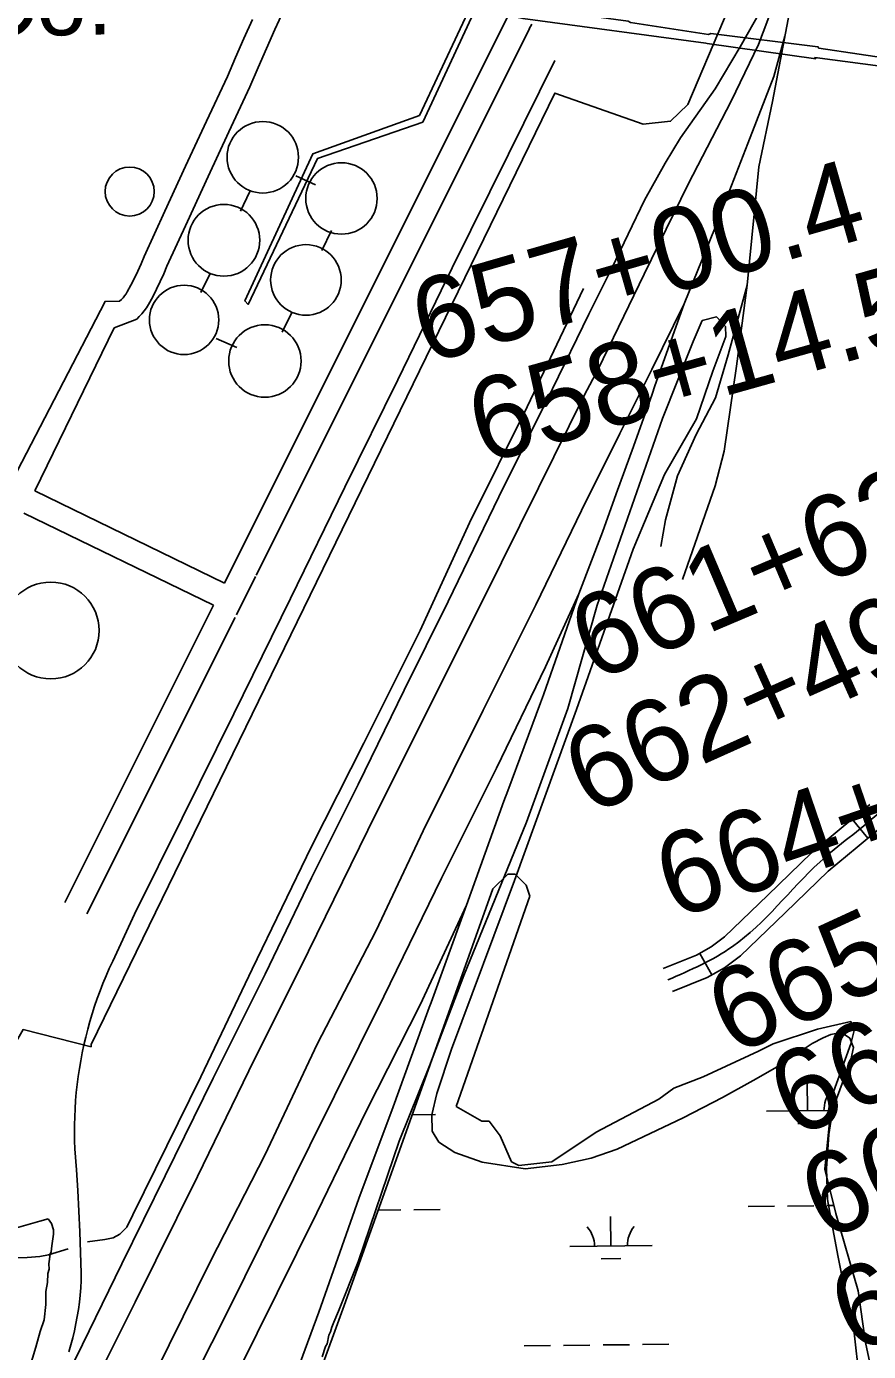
# Model space of a CAD drawing. Extents: x 3625074 to 3663148, y 511451 to 537151.
# Drawn here: x 3656305 to 3657328, y 518099 to 519708 of the extents above; entities that cross this region are included whole.
import ezdxf

# ---------------------------------------------------------------- set-up
doc = ezdxf.new("R2010")
doc.units = 0
for name, color, linetype in [('V-BLDG-IDEN', 7, 'Continuous'), ('V-DOMW-TANK', 7, 'Continuous'), ('V-RAIL-TRAK', 7, 'Continuous'), ('V-ROAD-CNTR', 7, 'Continuous'), ('V-SITE-OTLN', 7, 'Continuous'), ('V-SITE-VEGE', 7, 'Continuous'), ('V-SURV-IDEN', 7, 'Continuous'), ('V-TOPO-SHOR', 7, 'Continuous'), ('V-UTIL-LINE', 7, 'Continuous'), ('V-WETL-SWMP', 7, 'Continuous')]:
    doc.layers.add(name, color=color, linetype=linetype)

msp = doc.modelspace()

# ---------------------------------------------------------------- linework, layer by layer
at = {"layer": 'V-DOMW-TANK'}
for centre, radius in [((3656591.6538281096, 519549.49129885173), 43.424167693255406), ((3656429.9732665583, 519507.77570504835), 29.80810737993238), ((3656687.2301187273, 519499.4398599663), 43.37723661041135), ((3656544.445555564, 519448.61488410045), 43.558219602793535), ((3656644.1125855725, 519400.44507197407), 42.881477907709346), ((3656496.0472769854, 519351.92765908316), 42.10919878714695), ((3656594.2244595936, 519301.97549370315), 43.996236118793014), ((3656334.055766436, 518974.54792726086), 58.795414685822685)]:
    msp.add_circle(centre, radius, dxfattribs=at)
at = {"layer": 'V-RAIL-TRAK'}
for points in [[(3657229.676, 520658.132), (3657252.8000000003, 520496.53), (3657273.728, 520344.41500000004), (3657279.9220000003, 520260.462), (3657282.686, 520183.066), (3657281.509, 520116.364), (3657270.703, 520006.143), (3657266.718, 519958.156), (3657253.099, 519855.66000000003), (3657233.241, 519734.37700000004), (3657211.096, 519617.26900000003), (3657194.342, 519537.853), (3657179.991, 519394.039), (3657167.034, 519295.661), (3657152.223, 519192.59500000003), (3657141.438, 519150.27400000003), (3657101.637, 519036.429)], [(3656987.836, 519358.805), (3657015.6210000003, 519414.658), (3657055.4590000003, 519497.207), (3657080.463, 519542.23000000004), (3657099.313, 519573.19), (3657141.1040000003, 519632.678), (3657171.525, 519683.507), (3657197.1210000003, 519728.52), (3657216.19, 519771.876), (3657236.713, 519830.56), (3657251.932, 519889.925), (3657266.718, 519958.156)], [(3656982.394, 519261.009), (3656999.284, 519292.132), (3657055.0530000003, 519407.465), (3657108.356, 519516.93700000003), (3657160.912, 519617.566), (3657194.018, 519686.653), (3657205.176, 519716.568), (3657235.197, 519811.691), (3657251.932, 519889.925)], [(3656975.744, 519019.01300000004), (3657004.232, 519094.087), (3657021.146, 519140.488), (3657042.085, 519197.928), (3657064.644, 519261.82), (3657068.1890000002, 519271.863), (3657103.609, 519371.613), (3657141.264, 519464.238), (3657180.856, 519566.278), (3657212.407, 519647.792), (3657226.076, 519696.487)], [(3656355.954, 518098.38800000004), (3656358.473, 518106.813), (3656360.771, 518115.302), (3656362.841, 518123.851), (3656364.687, 518132.44800000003), (3656366.305, 518141.09500000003), (3656367.693, 518149.778), (3656368.852, 518158.49700000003), (3656369.782, 518167.242), (3656370.481, 518176.007), (3656370.947, 518184.791), (3656371.183, 518193.581), (3656370.3880000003, 518218.78), (3656369.395, 518243.97000000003), (3656368.201, 518269.15), (3656366.806, 518294.322), (3656365.213, 518319.482), (3656363.419, 518344.62700000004), (3656363.0500000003, 518354.41500000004), (3656362.884, 518364.206), (3656362.921, 518374), (3656363.157, 518383.789), (3656363.595, 518393.574), (3656364.232, 518403.347), (3656365.072, 518413.104), (3656366.11, 518422.842), (3656367.349, 518432.556), (3656368.787, 518442.245), (3656370.423, 518451.89900000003), (3656372.256, 518461.521), (3656374.288, 518471.101), (3656376.5160000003, 518480.639), (3656378.9390000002, 518490.12700000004), (3656381.556, 518499.565), (3656384.3680000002, 518508.944), (3656387.3680000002, 518518.267), (3656390.561, 518527.526), (3656393.944, 518536.715), (3656397.5160000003, 518545.837), (3656401.272, 518554.881), (3656405.215, 518563.84500000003), (3656409.339, 518572.727), (3656435.816, 518630.047), (3656493.5300000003, 518746.37700000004), (3656556.642, 518873.216), (3656625.489, 519013.365), (3656691.232, 519148.65400000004), (3656755.8710000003, 519279.121), (3656821.6, 519415.20900000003), (3656890.0870000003, 519553.353), (3656946.659, 519666.86100000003)], [(3657075.183, 519076.457), (3657081.069, 519108.82800000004), (3657095.595, 519162.30100000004), (3657118.33, 519212.678), (3657141.555, 519257.142), (3657157.238, 519309.41500000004), (3657179.991, 519394.039)], [(3656310.816, 517982.139), (3656372.809, 518107.145), (3656420.482, 518205.281), (3656473.19, 518311.914), (3656531.257, 518430.653), (3656594.3740000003, 518557.091), (3656650.876, 518674.197), (3656707.454, 518787.306), (3656763.602, 518902.009), (3656817.086, 519009.856), (3656878.5870000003, 519137.064), (3656943.611, 519268.337), (3656987.836, 519358.805)], [(3656979.058, 519120.315), (3657025.5870000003, 519213.966), (3657064.161, 519291.815), (3657103.609, 519371.613)], [(3655986.384, 517252.59500000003), (3656035.112, 517350.036), (3656107.0500000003, 517495.846), (3656160.204, 517600.087), (3656222.482, 517728.509), (3656286.7600000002, 517856.97000000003), (3656356.769, 517999.142), (3656436.436, 518158.704), (3656512.239, 518311.39), (3656574.525, 518439.411), (3656647.27, 518584.837), (3656719.183, 518731.847), (3656791.9280000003, 518877.273), (3656858.896, 519011.386), (3656926.615, 519147.914), (3656982.394, 519261.009)], [(3655992.255561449, 517127.89855132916), (3656024.125, 517191.59500000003), (3656102.625, 517349.533), (3656167.294, 517478.401), (3656227.723, 517599.186), (3656290.778, 517728.822), (3656355.839, 517858.096), (3656414.668, 517978.85000000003), (3656477.755, 518106.887), (3656528.549, 518209.082), (3656594.417, 518337.97500000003), (3656657.786, 518472.017), (3656729.472, 518610.222), (3656786.696, 518731.34500000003), (3656859.424, 518877.57), (3656923.309, 519005.623), (3656979.058, 519120.315)], [(3656448.759, 517948.681), (3656550.025, 518149.068), (3656648.9, 518349.006), (3656738.5470000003, 518529.963), (3656808.9250000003, 518673.743), (3656875.4990000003, 518807.449), (3656935.0870000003, 518930.216), (3656975.744, 519019.01300000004), (3656932.609, 518896.348), (3656929.146, 518886.499), (3656889.347, 518779.727), (3656884.688, 518767.23000000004), (3656838.983, 518640.82300000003), (3656835.745, 518631.869), (3656796.288, 518522.697), (3656793.98, 518516.37), (3656770.86, 518453.01300000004), (3656749.9790000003, 518395.788), (3656708.562, 518284.57800000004), (3656659.677, 518146.42), (3656609.924, 518011.444)], [(3656335.179, 517612.148), (3656389.4390000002, 517721.21), (3656457.549, 517858.145), (3656534.017, 518017.646), (3656584.787, 518121.041), (3656657.518, 518267.266), (3656717.483, 518391.242), (3656782.96, 518519.72500000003), (3656838.983, 518640.82300000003)]]:
    msp.add_lwpolyline(points, dxfattribs=at)
at = {"layer": 'V-ROAD-CNTR'}
for p, q in [((3657307.593, 518745.275), (3657326.81, 518722.239)), ((3657122.543, 518582.326), (3657137.1410000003, 518556.117))]:
    msp.add_line(p, q, dxfattribs=at)
for points in [[(3656579.1218022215, 519717.0201217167), (3656568.696051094, 519693.83725817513), (3656558.4944061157, 519670.55469874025), (3656548.642780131, 519647.4768950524), (3656523.286714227, 519593.22443723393), (3656497.9714443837, 519538.64704913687), (3656472.814376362, 519483.997799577), (3656447.7203644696, 519429.0706216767), (3656443.867774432, 519419.8423012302), (3656439.958806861, 519411.1222966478), (3656435.823743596, 519402.5102229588), (3656431.463782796, 519394.00647394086), (3656427.0209933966, 519385.86757460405), (3656425.508412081, 519383.4746030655), (3656423.838353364, 519381.14765967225), (3656422.027085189, 519378.9184065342), (3656420.0937720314, 519376.8000946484), (3656417.7275075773, 519374.50241756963)], [(3656616.952163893, 519727.3976333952), (3656606.4221977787, 519704.5818782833), (3656596.115948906, 519681.6647418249), (3656586.0295938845, 519658.64530125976), (3656576.0352198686, 519635.2331049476), (3656550.4832857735, 519580.5615627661), (3656525.2045556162, 519526.06295086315), (3656500.0836236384, 519471.49220042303), (3656475.2136355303, 519417.0553783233), (3656471.402225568, 519407.9256987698), (3656467.173193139, 519398.49170335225), (3656462.698256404, 519389.1717770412), (3656457.9822172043, 519379.9735260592), (3656452.8930066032, 519370.650425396), (3656450.3955879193, 519366.69939693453), (3656447.6876466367, 519362.9263403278), (3656444.766914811, 519359.3315934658), (3656441.6422279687, 519355.90790535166), (3656438.6264924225, 519352.9795824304)], [(3656888.7460000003, 519719.108), (3656545.285, 519032.215)], [(3656915.578, 519705.69200000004), (3656583.545, 519041.653)], [(3656918.438, 519711.042), (3656916.949, 519708.304), (3656915.452, 519705.444)], [(3656287.5700000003, 519157.31200000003), (3656400.1684689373, 519374.43589152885), (3656417.7275075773, 519374.50241756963)], [(3656314.559, 519144.212), (3656411.250319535, 519342.270033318), (3656438.6264924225, 519352.9795824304)], [(3656545.286, 519032.215), (3656314.559, 519144.212)], [(3656531.8680000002, 519005.38), (3656301.328, 519117.287)], [(3656582.771, 519040.104), (3656559.536, 518993.637)], [(3656531.8680000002, 519005.381), (3656351.132, 518643.923)], [(3656557.987, 518990.539), (3656377.964, 518630.507)], [(3657078.137, 518563.982), (3657118.754, 518580.215), (3657136.432, 518590.06200000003), (3657152.818, 518602.204), (3657205.448, 518652.962), (3657258.457, 518704.393), (3657294.434, 518734.299), (3657329.236, 518763.33)], [(3657089.271, 518536.124), (3657131.6720000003, 518553.071), (3657152.73, 518564.8), (3657172.242, 518579.26), (3657226.306, 518631.4), (3657278.521, 518682.059), (3657313.632, 518711.245), (3657349.822, 518741.436)]]:
    msp.add_lwpolyline(points, dxfattribs=at)
msp.add_spline([(3657083.704, 518550.053), (3657162.5300000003, 518590.732), (3657268.489, 518693.226), (3657339.529, 518752.38300000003), (3657467.491, 518888.961), (3657603.938, 518969.882), (3657666.093, 519006.418), (3657661.7600000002, 519045.129), (3657632.7490000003, 519137.575), (3657617.309, 519293.58400000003), (3657611.131, 519436.401), (3657605.707, 519540.387), (3657573.915, 519600.772), (3657531.031, 519687.791)], degree=3, dxfattribs=at)
at = {"layer": 'V-SITE-OTLN'}
msp.add_lwpolyline([(3657238.198, 519920.066), (3657108.16, 519613.574), (3657087.029, 519593.178), (3657053.732, 519589.613), (3656946.394, 519627.511), (3656383.164, 518471.54600000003), (3656383.117, 518468.77900000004), (3656300.4020000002, 518489.626), (3656206.106, 518325.128), (3656076.1210000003, 518648.675), (3655761.606, 519264.886), (3655761.704, 519270.424), (3655868.659, 519289.304), (3655904.724, 519292.82), (3655925.286, 519318.99), (3655940.1380000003, 519337.891), (3656094.248, 519674.418), (3656105.396, 519678.375), (3656240.136, 519702.304), (3656283.291, 519715.38800000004)], dxfattribs=at)
at = {"layer": 'V-SITE-VEGE'}
for p, q in [((3657114.539, 519325.85899999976), (3657125.3000000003, 519351.305)), ((3657125.3000000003, 519351.305), (3657142.718, 519355.651)), ((3657142.718, 519355.651), (3657153.838, 519344.092)), ((3657153.838, 519344.092), (3657154.076, 519331.919)), ((3657077.319, 519231.96), (3657114.539, 519325.85899999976)), ((3657154.076, 519331.919), (3657138.44, 519289.675)), ((3657138.44, 519289.675), (3657118.58, 519231.84500000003)), ((3656997.869, 519005.373), (3657077.319, 519231.96)), ((3657118.58, 519231.84500000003), (3657079.648, 519164.112)), ((3657079.648, 519164.112), (3657041.522, 519073.441)), ((3657041.522, 519073.441), (3656972.666, 518878.625)), ((3656962.424, 518879.624), (3656997.869, 519005.373)), ((3656972.666, 518878.625), (3656897.363, 518670.876)), ((3656912.213, 518741.528), (3656962.424, 518879.624)), ((3656835.884, 518555.409), (3656912.213, 518741.528)), ((3656897.363, 518670.876), (3656820.799, 518466.11)), ((3656794.1380000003, 518445.74100000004), (3656835.884, 518555.409)), ((3657216.626, 518444.543), (3657259.2120000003, 518472.836)), ((3657259.2120000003, 518472.836), (3657272.377, 518479.719)), ((3657272.377, 518479.719), (3657281.933, 518483.69900000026)), ((3657281.933, 518483.699), (3657292.048, 518485.89199999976)), ((3657292.048, 518485.89199999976), (3657297.36, 518484.612)), ((3657297.36, 518484.612), (3657304.971, 518479.14400000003)), ((3657304.971, 518479.14400000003), (3657309.5130000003, 518467.798)), ((3656820.799, 518466.11), (3656803.215, 518412.244)), ((3657309.5130000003, 518467.798), (3657306.287, 518453.036)), ((3656757.446, 518354.21400000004), (3656794.1380000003, 518445.74100000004)), ((3657187.282, 518427.87), (3657216.626, 518444.543)), ((3657306.287, 518453.036), (3657298.186, 518430.651)), ((3657150.162, 518407.18499999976), (3657187.282, 518427.87)), ((3657298.186, 518430.651), (3657287.608, 518402.385)), ((3656803.215, 518412.244), (3656797.11, 518386.26299999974)), ((3657102.3030000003, 518382.54000000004), (3657150.162, 518407.18499999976)), ((3657287.608, 518402.385), (3657281.845, 518378.18200000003)), ((3656797.11, 518386.26299999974), (3656797.4990000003, 518366.42600000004)), ((3657022.191, 518344.238), (3657102.3030000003, 518382.54000000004)), ((3657281.845, 518378.18200000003), (3657279.1920000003, 518362.22399999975)), ((3656797.4990000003, 518366.42600000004), (3656805.5840000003, 518352.7539999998)), ((3657279.1920000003, 518362.22399999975), (3657278.275, 518343.86100000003)), ((3656707.401, 518207.7), (3656757.446, 518354.21400000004)), ((3656805.5840000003, 518352.7539999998), (3656825.069, 518340.507)), ((3656990.582, 518333.533), (3657022.191, 518344.238)), ((3657278.275, 518343.86100000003), (3657276.682, 518320.77)), ((3656825.069, 518340.507), (3656858.38, 518328.53399999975)), ((3656858.38, 518328.53399999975), (3656910.253, 518320.5299999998)), ((3656955.256, 518325.624), (3656990.582, 518333.5330000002)), ((3656910.253, 518320.53), (3656955.256, 518325.624)), ((3657276.682, 518320.77), (3657277.8000000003, 518283.40400000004)), ((3657277.8000000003, 518283.40400000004), (3657283.215, 518254.259)), ((3656289.693, 518247.878), (3656320.7490000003, 518257.07300000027)), ((3656320.7490000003, 518257.07300000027), (3656330.85, 518259.613)), ((3656330.85, 518259.613), (3656334.862, 518254.224)), ((3656334.862, 518254.224), (3656337.3540000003, 518246.46400000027)), ((3657283.215, 518254.259), (3657290.786, 518213.22299999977)), ((3656337.461, 518241.00200000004), (3656335.394, 518226.906)), ((3656337.3540000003, 518246.46400000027), (3656337.461, 518241.00200000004)), ((3656333.248, 518216.713), (3656331.919, 518204.974)), ((3656334.7490000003, 518219.865), (3656333.248, 518216.713)), ((3656335.394, 518226.906), (3656334.7490000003, 518219.865)), ((3656331.919, 518204.974), (3656332.04, 518198.73000000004)), ((3656683.474, 518147.489), (3656707.401, 518207.7)), ((3657290.786, 518213.22299999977), (3657296.77, 518182.8839999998)), ((3656330.585, 518193.2350000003), (3656330.018, 518182.292)), ((3656332.04, 518198.73000000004), (3656330.585, 518193.2350000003)), ((3657296.77, 518182.8839999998), (3657303.973, 518154.3)), ((3656330.018, 518182.292), (3656327.89, 518171.319)), ((3656327.89, 518171.319), (3656328.1950000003, 518155.707)), ((3656328.1950000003, 518155.707), (3656326.219, 518136.929)), ((3657303.973, 518154.3), (3657308.909, 518131.688)), ((3656326.219, 518136.929), (3656321.0300000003, 518122.77100000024)), ((3656677.924, 518134.41000000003), (3656683.474, 518147.489)), ((3656321.0300000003, 518122.77100000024), (3656315.932, 518103.93200000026)), ((3656672.083, 518118.29000000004), (3656673.845, 518122.634)), ((3656673.845, 518122.634), (3656675.583, 518128.211)), ((3656675.583, 518128.211), (3656677.924, 518134.41000000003)), ((3657308.909, 518131.688), (3657314.5470000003, 518081.793)), ((3656315.932, 518103.93200000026), (3656307.865, 518077.226)), ((3656663.973, 518092.277), (3656668.041, 518104.667)), ((3656668.041, 518104.667), (3656669.826, 518107.78)), ((3656669.826, 518107.78), (3656672.083, 518118.29000000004))]:
    msp.add_line(p, q, dxfattribs=at)
at = {"layer": 'V-TOPO-SHOR'}
for points in [[(3656981.446, 519390.25200000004), (3656912.721, 519246.204), (3656842.7290000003, 519105.344), (3656782.987, 518974.737), (3656714.5300000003, 518837.528), (3656650.667, 518712.065), (3656578.824, 518563.13), (3656516.269, 518432.468), (3656433.94, 518264.835), (3656426.598, 518249.819), (3656417.9220000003, 518241.207), (3656409.972, 518236.63), (3656399.9590000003, 518234.826), (3656378.7090000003, 518231.995)], [(3656355.159, 518223.494), (3656331.186, 518216.191), (3656320.778, 518213.97500000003), (3656305.524, 518212.873), (3656290.6580000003, 518212.58), (3656273.774, 518212.652), (3656264.161, 518210.856), (3656258.576, 518208.734), (3656247.836, 518202.897), (3656240.287, 518198.326), (3656237.973, 518193.458), (3656238.114, 518186.22500000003), (3656268.6210000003, 518106.43), (3656281.276, 518076.128)]]:
    msp.add_lwpolyline(points, dxfattribs=at)
at = {"layer": 'V-UTIL-LINE'}
for p, q in [((3656631.67, 519527.083), (3656655.671, 519515.80700000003)), ((3656564.42, 519484.063), (3656575.9930000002, 519507.92600000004)), ((3656663.531, 519436.32), (3656675.258, 519460.50200000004)), ((3656516.5700000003, 519385.39400000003), (3656528.144, 519409.257)), ((3656615.37, 519337.012), (3656627.255, 519361.517)), ((3656535.222, 519329.357), (3656560.037, 519318.488))]:
    msp.add_line(p, q, dxfattribs=at)
for points in [[(3656908.6380000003, 519732.315), (3656855.9960000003, 519758.4), (3656781.936, 519600.403), (3656652.552, 519553.781), (3656569.739, 519374.978), (3656573.855, 519370.71400000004), (3656658.04, 519548.09500000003), (3656785.9790000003, 519591.947), (3656858.617, 519748.57), (3656902.231, 519719.157)], [(3656908.6380000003, 519732.315), (3656910.169, 519731.672), (3657035.511, 519714.94800000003), (3657038.565, 519713.041), (3657133.08, 519698.716), (3657136.1890000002, 519699.895), (3657266.169, 519683.708), (3657267.068, 519682.147), (3657365.282, 519667.447)], [(3657357.397, 519658.018), (3657262.546, 519670.805), (3657263.4450000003, 519669.24700000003), (3657131.65, 519687.628), (3657130.112, 519687.96400000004), (3656907.769, 519718.13300000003), (3656902.231, 519719.157)]]:
    msp.add_lwpolyline(points, dxfattribs=at)
at = {"layer": 'V-WETL-SWMP'}
for p, q in [((3656871.2818486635, 518660.6939960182), (3656889.206829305, 518678.6199955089)), ((3656889.206829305, 518678.6199955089), (3656898.169819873, 518678.61999526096)), ((3656898.169819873, 518678.61999526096), (3656911.6148060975, 518665.1759948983)), ((3656692.02305119, 518158.77100134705), (3656871.2818486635, 518660.6939960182)), ((3656916.0958017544, 518651.7309947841), (3656826.4669031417, 518396.28799745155)), ((3656911.6148060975, 518665.1759948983), (3656916.0958017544, 518651.7309947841)), ((3657211.871495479, 518472.47298672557), (3657265.649438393, 518490.3989852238)), ((3657265.649438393, 518490.3989852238), (3657305.9823957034, 518499.3619841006)), ((3657305.9823957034, 518499.3619841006), (3657310.4633912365, 518490.39898398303)), ((3657310.4633912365, 518490.39898398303), (3657305.982396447, 518472.47298412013)), ((3657193.94551459, 518463.5099872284), (3657211.871495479, 518472.47298672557)), ((3657305.982396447, 518472.47298412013), (3657283.575421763, 518409.73298478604)), ((3657126.7245861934, 518432.1399891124), (3657193.94551459, 518463.5099872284)), ((3657090.8726242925, 518418.69599011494), (3657126.7245861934, 518432.1399891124)), ((3657253.504113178, 518390.98317561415), (3657253.1428258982, 518426.9813626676)), ((3657072.9466435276, 518405.2509906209), (3657090.8726242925, 518418.69599011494)), ((3657283.575421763, 518409.73298478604), (3657274.6124336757, 518320.1039850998)), ((3656826.4669031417, 518396.28799745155), (3656857.8368706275, 518378.3619965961)), ((3656996.761724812, 518364.9179927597), (3657072.9466435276, 518405.2509906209)), ((3656773.234770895, 518386.163074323), (3656801.6191088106, 518386.44794652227)), ((3656857.8368706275, 518378.3619965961), (3656866.799861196, 518378.36199634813)), ((3656866.799861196, 518378.36199634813), (3656880.244847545, 518360.4369959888)), ((3657203.5066574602, 518390.4813888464), (3657281.7287496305, 518391.2664450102)), ((3656880.244847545, 518360.4369959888), (3656893.6888342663, 518329.0659956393)), ((3656942.9847823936, 518329.0659942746), (3656996.761724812, 518364.9179927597)), ((3657241.659585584, 518375.4325238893), (3657265.6583643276, 518375.6733815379)), ((3656893.6888342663, 518329.0659956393), (3656902.651824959, 518324.5849953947)), ((3656902.651824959, 518324.5849953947), (3656942.9847823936, 518329.0659942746)), ((3657274.6124336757, 518320.1039850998), (3657288.056421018, 518266.3259847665)), ((3656731.858537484, 518270.30999891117), (3656759.3717652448, 518270.58612843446)), ((3656775.3709510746, 518270.7467002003), (3656807.3693227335, 518271.06784373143)), ((3657181.258296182, 518274.82028546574), (3657213.256667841, 518275.1414289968)), ((3657229.25585367, 518275.3020007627), (3657261.2542253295, 518275.6231442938)), ((3657277.253411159, 518275.7837160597), (3657285.6709590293, 518275.8681966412)), ((3657288.056421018, 518266.3259847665), (3657314.945395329, 518172.2159840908)), ((3657014.6687575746, 518226.716013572), (3657014.307470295, 518262.7142006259)), ((3656964.6713018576, 518226.2142268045), (3657064.666213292, 518227.21780033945)), ((3657002.8242299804, 518211.16536184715), (3657026.823008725, 518211.4062194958)), ((3657314.945395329, 518172.2159840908), (3657323.9083876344, 518109.4749838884)), ((3656481.395288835, 517580.6630075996), (3656692.02305119, 518158.77100134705)), ((3656909.0351978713, 518105.5788021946), (3656941.0335695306, 518105.8999457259)), ((3656957.0327553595, 518106.06051749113), (3656989.031127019, 518106.38166102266)), ((3657005.030312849, 518106.54223278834), (3657037.028684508, 518106.86337631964)), ((3657053.0278703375, 518107.0239480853), (3657085.026241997, 518107.3450916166)), ((3657323.9083876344, 518109.4749838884), (3657337.3523752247, 518046.7349835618))]:
    msp.add_line(p, q, dxfattribs=at)
for centre, radius, start, end in [((3657198.2592231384, 518390.9035513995), 35.24628790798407, 359.803194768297, 41.3468531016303), ((3657308.7394731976, 518392.0123583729), 35.24628790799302, 139.80319257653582, 181.34685090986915), ((3656959.423867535, 518226.6363893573), 35.24628790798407, 359.803194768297, 41.3468531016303), ((3657069.9041175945, 518227.74519633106), 35.24628790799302, 139.80319257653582, 181.34685090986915)]:
    msp.add_arc(centre, radius, start, end, dxfattribs=at)

# ---------------------------------------------------------------- texts
at = {"layer": 'V-BLDG-IDEN'}
msp.add_text('Oil Co.', height=82.99983200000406, rotation=1.0368000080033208, dxfattribs=at).set_placement((3656070.171820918, 519692.76958826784))
at = {"layer": 'V-SURV-IDEN'}
for s, height, rotation, p in [('657+00.4', 100.00000000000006, 16.03383798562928, (3656790.519165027, 519297.9671529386)), ('658+14.5', 100, 15.659260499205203, (3656858.881645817, 519176.6380475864)), ('661+62.6', 100.00000000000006, 22.990082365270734, (3656993.726327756, 518911.5390704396)), ('662+49.2', 100.00000000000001, 24.173238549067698, (3656987.9352855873, 518749.2602681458)), ('664+29.1', 100.00000000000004, 18.833108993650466, (3657091.037624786, 518623.0171176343)), ('665+34.0', 99.99999999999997, 24.719953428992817, (3657162.876686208, 518457.1785380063)), ('667+31.6', 100.00000000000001, 23.965303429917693, (3657236.9623173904, 518357.03485206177)), ('667+87.4', 100.00000000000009, 23.565555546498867, (3657274.1238372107, 518232.1161677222)), ('668+30.8', 100.00000000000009, 23.947570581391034, (3657310.9828114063, 518094.7451387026))]:
    msp.add_text(s, height=height, rotation=rotation, dxfattribs=at).set_placement(p)

doc.saveas('drawing.dxf')
